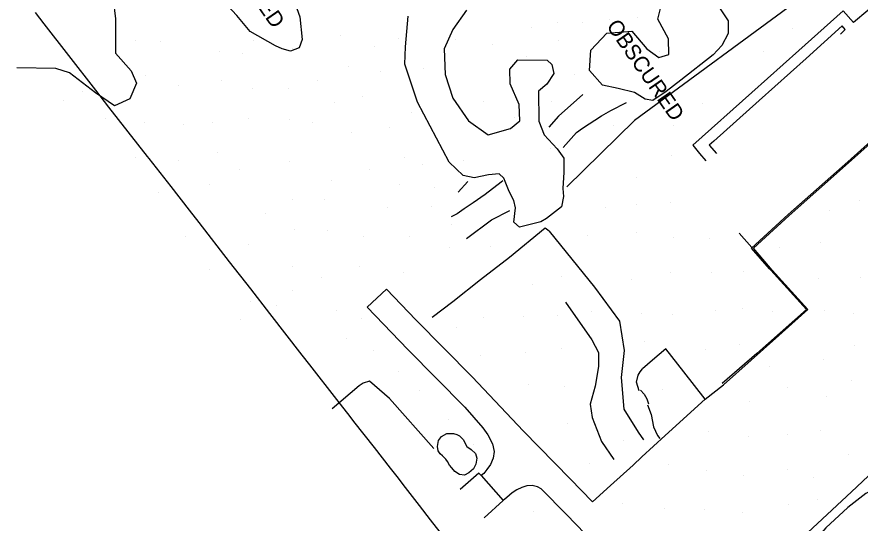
# Model space of a CAD drawing. Extents: x 1497074 to 1501343, y 481943 to 486114.
# Drawn here: x 1497098.6 to 1497425.4, y 484050.2 to 484246.4 of the extents above; entities that cross this region are included whole.
import ezdxf

# ---------------------------------------------------------------- set-up
doc = ezdxf.new("R2010")
doc.units = 0
for name, color, linetype in [('PH Exist DTM Boundary', 7, 'Continuous'), ('PH Exist DTM Breakline', 7, 'Continuous'), ('PH Exist DTM Obscure Area', 7, 'Continuous'), ('PH Exist DTM Obscure Area Text', 7, 'Continuous'), ('PH Exist DTM Point', 7, 'Continuous')]:
    doc.layers.add(name, color=color, linetype=linetype)

msp = doc.modelspace()

# ---------------------------------------------------------------- linework, layer by layer
at = {"layer": 'PH Exist DTM Boundary'}
msp.add_lwpolyline([(1497105.67, 484248.08), (1497109.09, 484243.69), (1497118.59, 484231.49), (1497129.09, 484218.01), (1497134.17, 484211.49), (1497149.09, 484192.33), (1497149.75, 484191.49), (1497158.22, 484180.62), (1497165.32, 484171.49), (1497169.09, 484166.66), (1497180.9, 484151.49), (1497189.09, 484140.98), (1497196.48, 484131.49), (1497209.09, 484115.3), (1497212.06, 484111.49), (1497222.51, 484098.07), (1497227.63, 484091.49), (1497229.09, 484089.62), (1497237.03, 484079.43), (1497243.21, 484071.49), (1497245.79, 484068.19), (1497249.09, 484063.95), (1497254.54, 484056.94), (1497258.79, 484051.49), (1497269.09, 484038.27)], dxfattribs=at)
at = {"layer": 'PH Exist DTM Breakline'}
for points in [[(1497423.6, 484275.1), (1497416.57, 484267.88), (1497403.75, 484254.79), (1497337.98, 484206.23), (1497311.68, 484180.57)], [(1497437.56, 484251.09), (1497434.71, 484254.45), (1497428.34, 484248.9), (1497422.88, 484244.21), (1497418.82, 484248.83), (1497401.66, 484233.36), (1497383.44, 484217.08), (1497360.56, 484196.64), (1497363.2, 484193.52), (1497365.66, 484190.68)], [(1497417.77, 484239.78), (1497419.66, 484241.48), (1497418.48, 484242.91), (1497404.44, 484230.26), (1497386.22, 484213.97), (1497368.7, 484198.27), (1497366.91, 484196.73), (1497369.78, 484193.51)], [(1497420.57, 484190.27), (1497440.78, 484208.31), (1497460.32, 484226.01), (1497455.43, 484231.52), (1497446.51, 484241.16)], [(1497420.9, 484189.9), (1497441.12, 484207.94), (1497460.96, 484225.86), (1497455.78, 484231.83), (1497446.65, 484241.78)], [(1497317.92, 484216.39), (1497308.45, 484207.93), (1497304.79, 484203.72)], [(1497310.26, 484195.78), (1497315.47, 484201.56), (1497317.75, 484203.34), (1497325.19, 484208.07), (1497328.76, 484210.17), (1497334.91, 484213.29)], [(1497390.76, 484148.19), (1497390.31, 484148.7), (1497383.36, 484156.8), (1497397.55, 484169.79), (1497420.57, 484190.27)], [(1497391.36, 484148.27), (1497390.68, 484149.03), (1497384.05, 484156.76), (1497397.89, 484169.42), (1497420.9, 484189.9)], [(1497286.96, 484182.83), (1497286.33, 484182.35), (1497280.13, 484177.59), (1497275.4, 484174.32), (1497272, 484172.01), (1497269.26, 484170.11), (1497266.86, 484168.9)], [(1497269.62, 484178.49), (1497273.41, 484182.67)], [(1497272.8, 484160.51), (1497282.53, 484167.71), (1497289.64, 484171.37)], [(1497304.93, 484163.33), (1497303.34, 484164.55), (1497289.48, 484153.21), (1497278.3, 484144.54), (1497267.61, 484135.97), (1497259.5, 484129.94)], [(1497304.93, 484163.33), (1497322.51, 484141.59), (1497332.09, 484128.52), (1497333.97, 484117.06), (1497332.77, 484106.66), (1497333.85, 484094.36), (1497339.37, 484085.47), (1497341.41, 484082.52)], [(1497383.49, 484157), (1497378.55, 484162.55)], [(1497390.76, 484148.19), (1497404.62, 484133.02)], [(1497405.13, 484133.01), (1497391.36, 484148.27)], [(1497548.27, 484125.17), (1497547.78, 484127.26), (1497546.11, 484130.51), (1497543.16, 484134.18), (1497539.75, 484136.98), (1497532.88, 484140.81), (1497525.69, 484144.59), (1497519.72, 484146.75), (1497515.96, 484148.04), (1497507.8, 484141.08), (1497493.83, 484127.89), (1497474.93, 484111.24), (1497461.22, 484098.34), (1497441.57, 484080.6), (1497422.07, 484062.26), (1497399.5, 484041.18)], [(1497234.4, 484133.84), (1497241.84, 484140.81), (1497253.25, 484129.03), (1497275.05, 484106.83), (1497294.93, 484085.85), (1497313.01, 484067.33), (1497321.69, 484058.46), (1497328.65, 484064.77), (1497337.41, 484072.7), (1497340.85, 484075.9), (1497349.88, 484084.16), (1497365.39, 484098.2)], [(1497234.4, 484133.84), (1497250.1, 484117.47), (1497272.17, 484095.15), (1497279.24, 484087.13), (1497281.17, 484084.35), (1497282.88, 484080.93), (1497283.52, 484077.99), (1497283.15, 484075.41), (1497282.13, 484072.91), (1497280.74, 484071), (1497279.58, 484069.44), (1497278.54, 484068.61)], [(1497311.25, 484135.79), (1497321.48, 484121.29), (1497323.96, 484116.27), (1497324.06, 484110.95), (1497322.77, 484103.24), (1497320.82, 484096.35), (1497321.54, 484091.07), (1497325.22, 484081.8), (1497329.94, 484074.85)], [(1497365.39, 484098.2), (1497372.48, 484103.73), (1497393.87, 484122.9), (1497405.13, 484133.01)], [(1497404.62, 484133.02), (1497385.39, 484115.91), (1497371.94, 484104.3)], [(1497365.39, 484098.2), (1497357.06, 484108.85), (1497350.13, 484117.69), (1497344.87, 484113.31), (1497341.09, 484109.95)], [(1497339.76, 484101.46), (1497338.69, 484104.81), (1497339.35, 484107.53), (1497340.17, 484108.87), (1497341.09, 484109.95)], [(1497260.19, 484079.09), (1497242.97, 484098.48), (1497235.31, 484105.23), (1497232.83, 484104.46), (1497231.27, 484103.45), (1497220.74, 484094.53)], [(1497340.32, 484101.66), (1497341.69, 484100.16), (1497342.75, 484098.32), (1497343.43, 484096.37)], [(1497342.95, 484096.06), (1497344.42, 484092.24), (1497345.32, 484087.46), (1497346.87, 484084.19), (1497347.81, 484083.01)], [(1497270.11, 484083.95), (1497271.66, 484082.47), (1497272.31, 484081.05), (1497272.97, 484079.93), (1497274.61, 484078.71), (1497276.38, 484077.13), (1497276.9, 484075.31), (1497276.5, 484073.05), (1497275.56, 484071.24), (1497273.79, 484069.65), (1497272.06, 484068.8), (1497270.14, 484069.07), (1497268.27, 484070.12), (1497267.11, 484071.54), (1497266.31, 484072.69), (1497265.45, 484074.07), (1497264.8, 484075.01), (1497263.5, 484076.28), (1497262.59, 484076.98), (1497261.82, 484078.2), (1497261.66, 484079.91), (1497261.94, 484082.16), (1497263.19, 484083.7), (1497265.25, 484084.91), (1497267.81, 484084.94), (1497269.09, 484084.57), (1497270.11, 484083.95)], [(1497278.54, 484068.61), (1497277.63, 484069.54), (1497273.54, 484065.91), (1497270.34, 484063.17)], [(1497278.54, 484068.61), (1497287, 484058.88)], [(1497326.06, 484038.55), (1497311.6, 484053.46), (1497301.78, 484063.49), (1497300.34, 484064.21), (1497298.27, 484064.75), (1497296.19, 484064.67), (1497294.27, 484064.03), (1497292.33, 484063.07), (1497290.55, 484061.92), (1497288.53, 484060.15), (1497287, 484058.88)], [(1497434.59, 484065.23), (1497427.56, 484061.64), (1497420.69, 484056.28), (1497412.17, 484048.37), (1497408.95, 484044.74), (1497408.71, 484043.55), (1497413.25, 484038.93), (1497417.39, 484037.66), (1497419.02, 484036.62)], [(1497287, 484058.88), (1497279.72, 484052.2)]]:
    msp.add_lwpolyline(points, dxfattribs=at)
at = {"layer": 'PH Exist DTM Obscure Area'}
for points in [[(1497198.87, 484235.26), (1497188.98, 484240.77), (1497183.88, 484246.95), (1497174.23, 484257.3), (1497169.92, 484264.98), (1497170.1, 484272.92), (1497174.72, 484275.58), (1497176.34, 484278.28), (1497174.16, 484283.29), (1497166.99, 484293.5), (1497166.79, 484296.87), (1497170.07, 484297.71), (1497176.43, 484293.96), (1497183.18, 484289.56), (1497187.53, 484282.09), (1497192.56, 484272.38), (1497198.64, 484263.69), (1497205.23, 484254.84), (1497208.21, 484246.51), (1497209.21, 484237.61), (1497208.02, 484234.48), (1497204.69, 484233.14), (1497201.39, 484234.11), (1497198.87, 484235.26)], [(1497135.89, 484253.35), (1497136.89, 484245.62), (1497136.88, 484232.41), (1497142.94, 484225.55), (1497144.93, 484220.77), (1497142.42, 484214.61), (1497136.49, 484211.89), (1497129.1, 484216.99), (1497118.94, 484224.7), (1497113.65, 484226.45), (1497098.6, 484226.7)], [(1497350.27, 484217.57), (1497345, 484213.97), (1497342.14, 484214.48), (1497337.9, 484217.13), (1497331.62, 484218.68), (1497325.62, 484219.99), (1497320.54, 484225.64), (1497321.08, 484233.52), (1497327.21, 484240.12), (1497336.93, 484240.88), (1497342.74, 484234.06), (1497347.44, 484230.75), (1497351.2, 484231.9), (1497351.13, 484237.94), (1497346.97, 484245.6), (1497348.49, 484251.78)], [(1497272.86, 484249.1), (1497267.53, 484241.48), (1497264.17, 484234.04), (1497264.56, 484224.11), (1497267.56, 484214.96), (1497273.69, 484206.09), (1497281.25, 484200.7), (1497289.91, 484203.1), (1497293.55, 484206.18), (1497293.21, 484212.43), (1497289.71, 484220.52), (1497289.66, 484226.21), (1497292.73, 484229.77), (1497304.12, 484229.65), (1497305.9, 484227.96), (1497306.75, 484224.54), (1497303.95, 484220.33), (1497300.8, 484217.66), (1497300.89, 484206.02), (1497303.01, 484200.77), (1497308.01, 484195.32), (1497310.52, 484191.62), (1497310.61, 484186.2), (1497310.19, 484179.86), (1497310.49, 484176.83), (1497309.61, 484172.8), (1497303.86, 484168.25), (1497301.65, 484166.94), (1497293.4, 484164.97), (1497291.15, 484166.9), (1497291.87, 484172.42), (1497291.25, 484175.21), (1497289.39, 484178.71), (1497287.3, 484183.87), (1497285.54, 484185.61), (1497281.43, 484185.2), (1497275.83, 484184), (1497271.51, 484184.94), (1497266.17, 484190.05), (1497253.8, 484213.31), (1497248.98, 484228.05), (1497249.15, 484234.83), (1497250.19, 484246.72)], [(1497370.93, 484249.88), (1497374.28, 484244.93), (1497374.29, 484240.05), (1497371.86, 484235.37), (1497368.38, 484231.75), (1497355.87, 484221.96), (1497350.27, 484217.57)]]:
    msp.add_lwpolyline(points, dxfattribs=at)
at = {"layer": 'PH Exist DTM Point'}
for p, q in [((1497328.24, 484245.52), (1497328.24, 484245.52)), ((1497339.23, 484246.13), (1497339.23, 484246.13)), ((1497298.09, 484242.22), (1497298.09, 484242.22)), ((1497308.3, 484244.18), (1497308.3, 484244.18)), ((1497317.66, 484244.09), (1497317.66, 484244.09)), ((1497399.3, 484242.01), (1497399.3, 484242.01)), ((1497223.96, 484239.39), (1497223.96, 484239.39)), ((1497246.52, 484238.23), (1497246.52, 484238.23)), ((1497268.46, 484237.81), (1497268.46, 484237.81)), ((1497144.41, 484237.21), (1497144.41, 484237.21)), ((1497154.45, 484237.01), (1497154.45, 484237.01)), ((1497190.38, 484237.37), (1497190.38, 484237.37)), ((1497237.31, 484234.85), (1497237.31, 484234.85)), ((1497282.86, 484235.64), (1497282.86, 484235.64)), ((1497308.48, 484237.31), (1497308.48, 484237.31)), ((1497177, 484233.08), (1497177, 484233.08)), ((1497185.99, 484232.25), (1497185.99, 484232.25)), ((1497205.44, 484234.09), (1497205.44, 484234.09)), ((1497296.1, 484231.16), (1497296.1, 484231.16)), ((1497347.7, 484232.88), (1497347.7, 484232.88)), ((1497387.85, 484233.18), (1497387.85, 484233.18)), ((1497226.94, 484227.16), (1497226.94, 484227.16)), ((1497239.33, 484225.13), (1497239.33, 484225.13)), ((1497256.18, 484226.45), (1497256.18, 484226.45)), ((1497148.41, 484223.55), (1497148.41, 484223.55)), ((1497177.72, 484221.69), (1497177.72, 484221.69)), ((1497214.95, 484221.78), (1497214.95, 484221.78)), ((1497314.52, 484223.95), (1497314.52, 484223.95)), ((1497161.28, 484219.85), (1497161.28, 484219.85)), ((1497189.89, 484218.85), (1497189.89, 484218.85)), ((1497203.99, 484218.67), (1497203.99, 484218.67)), ((1497124.2, 484217.37), (1497124.2, 484217.37)), ((1497232.66, 484215.72), (1497232.66, 484215.72)), ((1497116.53, 484213.95), (1497116.53, 484213.95)), ((1497221.65, 484213.18), (1497221.65, 484213.18)), ((1497279.46, 484213.52), (1497279.46, 484213.52)), ((1497305.83, 484213.61), (1497305.83, 484213.61)), ((1497364.17, 484212.9), (1497364.17, 484212.9)), ((1497251.42, 484209.39), (1497251.42, 484209.39)), ((1497132.88, 484207.16), (1497132.88, 484207.16)), ((1497147.99, 484205.63), (1497147.99, 484205.63)), ((1497174.46, 484205.59), (1497174.46, 484205.59)), ((1497188.45, 484206.93), (1497188.45, 484206.93)), ((1497204.33, 484206.73), (1497204.33, 484206.73)), ((1497213.04, 484205.47), (1497213.04, 484205.47)), ((1497291.51, 484207.57), (1497291.51, 484207.57)), ((1497163.28, 484204.54), (1497163.28, 484204.54)), ((1497243.07, 484203.49), (1497243.07, 484203.49)), ((1497330, 484204.36), (1497330, 484204.36)), ((1497352.99, 484204.43), (1497352.99, 484204.43)), ((1497228.47, 484201.48), (1497228.47, 484201.48)), ((1497305.23, 484195.27), (1497305.23, 484195.27)), ((1497144.43, 484192.08), (1497144.43, 484192.08)), ((1497176.33, 484193.99), (1497176.33, 484193.99)), ((1497248.74, 484192.09), (1497248.74, 484192.09)), ((1497352.14, 484192.67), (1497352.14, 484192.67)), ((1497161.33, 484190.64), (1497161.33, 484190.64)), ((1497204.44, 484190.56), (1497204.44, 484190.56)), ((1497255.81, 484189.36), (1497255.81, 484189.36)), ((1497271.6, 484190.89), (1497271.6, 484190.89)), ((1497185.06, 484187.29), (1497185.06, 484187.29)), ((1497235.33, 484187.32), (1497235.33, 484187.32)), ((1497220.5, 484182.86), (1497220.5, 484182.86)), ((1497338.54, 484184.22), (1497338.54, 484184.22)), ((1497173.44, 484181.5), (1497173.44, 484181.5)), ((1497247.07, 484181.51), (1497247.07, 484181.51)), ((1497260.54, 484180.42), (1497260.54, 484180.42)), ((1497153.63, 484178.18), (1497153.63, 484178.18)), ((1497205.4, 484175.81), (1497205.4, 484175.81)), ((1497217.94, 484175.64), (1497217.94, 484175.64)), ((1497242.23, 484172.59), (1497242.23, 484172.59)), ((1497259.37, 484173.03), (1497259.37, 484173.03)), ((1497326.57, 484172.71), (1497326.57, 484172.71)), ((1497338.84, 484173.56), (1497338.84, 484173.56)), ((1497352.07, 484174.55), (1497352.07, 484174.55)), ((1497425.03, 484175.15), (1497425.03, 484175.15)), ((1497195.11, 484170.36), (1497195.11, 484170.36)), ((1497413.39, 484171.32), (1497413.39, 484171.32)), ((1497266.92, 484165.89), (1497266.92, 484165.89)), ((1497206.28, 484164.12), (1497206.28, 484164.12)), ((1497218.83, 484163.49), (1497218.83, 484163.49)), ((1497338.56, 484162.85), (1497338.56, 484162.85)), ((1497163.98, 484161.26), (1497163.98, 484161.26)), ((1497232.76, 484161.23), (1497232.76, 484161.23)), ((1497250.94, 484161.42), (1497250.94, 484161.42)), ((1497319.59, 484161.83), (1497319.59, 484161.83)), ((1497352.92, 484161.07), (1497352.92, 484161.07)), ((1497366.93, 484160.43), (1497366.93, 484160.43)), ((1497188.22, 484158.21), (1497188.22, 484158.21)), ((1497266.43, 484156.89), (1497266.43, 484156.89)), ((1497282.08, 484157.51), (1497282.08, 484157.51)), ((1497394.26, 484157.19), (1497394.26, 484157.19)), ((1497409.93, 484158.85), (1497409.93, 484158.85)), ((1497205.45, 484149.85), (1497205.45, 484149.85)), ((1497231.57, 484149.81), (1497231.57, 484149.81)), ((1497173.42, 484148.67), (1497173.42, 484148.67)), ((1497248.37, 484147.31), (1497248.37, 484147.31)), ((1497351.99, 484147.36), (1497351.99, 484147.36)), ((1497367.67, 484147.26), (1497367.67, 484147.26)), ((1497380.18, 484147.63), (1497380.18, 484147.63)), ((1497216.84, 484145.34), (1497216.84, 484145.34)), ((1497309.84, 484145.69), (1497309.84, 484145.69)), ((1497336.79, 484144.52), (1497336.79, 484144.52)), ((1497409.11, 484144.99), (1497409.11, 484144.99)), ((1497425.39, 484145.21), (1497425.39, 484145.21)), ((1497205.57, 484140.38), (1497205.57, 484140.38)), ((1497298.24, 484142.61), (1497298.24, 484142.61)), ((1497189.09, 484136.23), (1497189.09, 484136.23)), ((1497199.34, 484134.59), (1497199.34, 484134.59)), ((1497379.97, 484133.29), (1497379.97, 484133.29)), ((1497222.31, 484132.49), (1497222.31, 484132.49)), ((1497279.62, 484129.95), (1497279.62, 484129.95)), ((1497294.89, 484130.19), (1497294.89, 484130.19)), ((1497308.06, 484130.62), (1497308.06, 484130.62)), ((1497321.4, 484132.32), (1497321.4, 484132.32)), ((1497340.59, 484131.63), (1497340.59, 484131.63)), ((1497352.69, 484131.15), (1497352.69, 484131.15)), ((1497369.48, 484132.5), (1497369.48, 484132.5)), ((1497391.54, 484132.09), (1497391.54, 484132.09)), ((1497411.55, 484132.79), (1497411.55, 484132.79)), ((1497422.97, 484131.47), (1497422.97, 484131.47)), ((1497185.11, 484129.17), (1497185.11, 484129.17)), ((1497232.24, 484129.63), (1497232.24, 484129.63)), ((1497268.84, 484125.98), (1497268.84, 484125.98)), ((1497226.23, 484121.66), (1497226.23, 484121.66)), ((1497341.73, 484120.72), (1497341.73, 484120.72)), ((1497236.98, 484117.16), (1497236.98, 484117.16)), ((1497309.69, 484117.99), (1497309.69, 484117.99)), ((1497365.33, 484117.67), (1497365.33, 484117.67)), ((1497378.63, 484119.49), (1497378.63, 484119.49)), ((1497423.24, 484119.03), (1497423.24, 484119.03)), ((1497278.31, 484115.12), (1497278.31, 484115.12)), ((1497295.66, 484116.49), (1497295.66, 484116.49)), ((1497411.34, 484113.77), (1497411.34, 484113.77)), ((1497390.17, 484110.78), (1497390.17, 484110.78)), ((1497246.55, 484109.11), (1497246.55, 484109.11)), ((1497296.79, 484103.85), (1497296.79, 484103.85)), ((1497422.06, 484105.48), (1497422.06, 484105.48)), ((1497254.47, 484101.58), (1497254.47, 484101.58)), ((1497311.02, 484103.16), (1497311.02, 484103.16)), ((1497348.8, 484102.1), (1497348.8, 484102.1)), ((1497397.15, 484102.88), (1497397.15, 484102.88)), ((1497382.7, 484097.25), (1497382.7, 484097.25)), ((1497412.33, 484099.41), (1497412.33, 484099.41)), ((1497265.71, 484090.31), (1497265.71, 484090.31)), ((1497311.92, 484088.64), (1497311.92, 484088.64)), ((1497366.47, 484085.61), (1497366.47, 484085.61)), ((1497397.41, 484084.36), (1497397.41, 484084.36)), ((1497410.03, 484085.96), (1497410.03, 484085.96)), ((1497333.8, 484082.06), (1497333.8, 484082.06)), ((1497381.95, 484083.88), (1497381.95, 484083.88)), ((1497275.58, 484080.56), (1497275.58, 484080.56)), ((1497420.88, 484076.86), (1497420.88, 484076.86)), ((1497320.35, 484073.37), (1497320.35, 484073.37)), ((1497351.1, 484073.04), (1497351.1, 484073.04)), ((1497397.08, 484071.15), (1497397.08, 484071.15)), ((1497365.81, 484070.42), (1497365.81, 484070.42)), ((1497380.34, 484068.62), (1497380.34, 484068.62)), ((1497407.27, 484067.82), (1497407.27, 484067.82)), ((1497408.92, 484059.29), (1497408.92, 484059.29)), ((1497298.77, 484054.8), (1497298.77, 484054.8)), ((1497333.22, 484057.82), (1497333.22, 484057.82)), ((1497349.64, 484055.92), (1497349.64, 484055.92)), ((1497365.25, 484055.49), (1497365.25, 484055.49)), ((1497397.46, 484057.3), (1497397.46, 484057.3)), ((1497379.92, 484054.37), (1497379.92, 484054.37))]:
    msp.add_line(p, q, dxfattribs=at)

# ---------------------------------------------------------------- texts
at = {"layer": 'PH Exist DTM Obscure Area Text'}
for p in [(1497172, 484278.87), (1497326.86, 484242.85)]:
    msp.add_text('OBSCURED', height=6, rotation=304.7435, dxfattribs=at).set_placement(p)

doc.saveas('drawing.dxf')
